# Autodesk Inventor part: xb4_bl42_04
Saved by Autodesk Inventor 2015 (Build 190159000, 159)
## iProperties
Created: 2018-05
Part Number: xb4_bl42_04
Checked By: TraceParts S.A.
Material: Generic
Catalog Web Link: www.traceparts.com
Document SubType Name: Modeling
Designer: TraceParts
Density: 1 g/cm^3
Appearance: Default
Company: TraceParts S.A.
Author: TraceParts
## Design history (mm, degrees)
feature "xb4_bl42_04.ipt"
body "Solid1"
